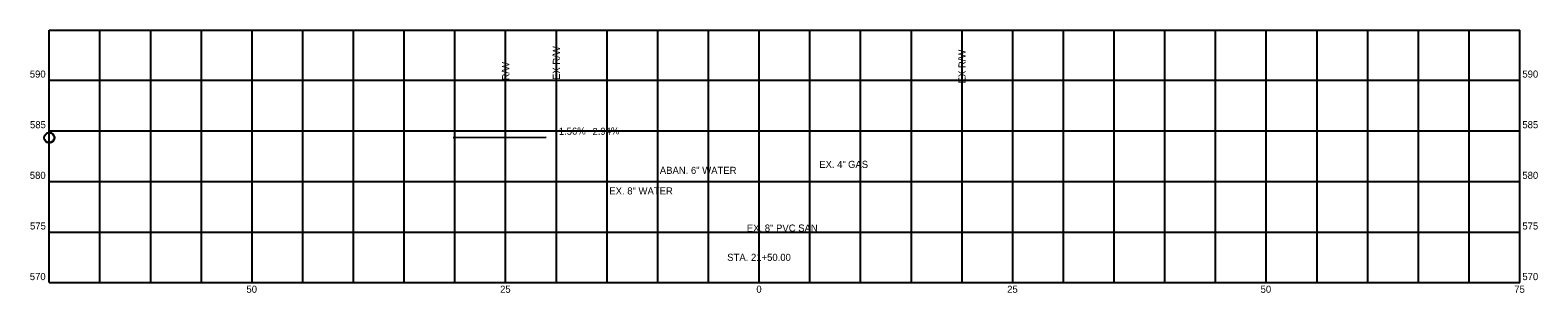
# Model space of a CAD drawing. Extents: x -72 to 1946739, y 569 to 153946.
# Drawn here: x -71.9 to 76.8, y 569 to 594.9 of the extents above; entities that cross this region are included whole.
import ezdxf

# ---------------------------------------------------------------- set-up
doc = ezdxf.new("R2010")
doc.units = 0
for name, color, linetype in [('Default', 7, 'Continuous'), ('DT_X_Contour_Major', 7, 'Continuous'), ('DT_X_Contour_Minor', 7, 'Continuous'), ('DT_X_Terrain_Boundary', 7, 'Continuous'), ('DT_X_Terrain_Ground_Line', 7, 'Continuous'), ('DT_X_Triangles', 7, 'Continuous'), ('DT_X_Void', 7, 'Continuous'), ('PV_X_Curb', 7, 'Continuous'), ('PV_X_EOP', 7, 'Continuous'), ('PV_X_Shoulder', 7, 'Continuous')]:
    doc.layers.add(name, color=color, linetype=linetype)

msp = doc.modelspace()

# ---------------------------------------------------------------- linework, layer by layer
at = {"layer": 'DT_X_Contour_Major'}
msp.add_line((-21.02, 584.32), (-30.18, 584.31), dxfattribs=at)
at = {"layer": 'DT_X_Contour_Minor'}
for p, q in [((-70, 594.94), (75, 594.94)), ((-70, 570), (-70, 594.94)), ((-65, 570), (-65, 594.94)), ((-60, 570), (-60, 594.94)), ((-55, 570), (-55, 594.94)), ((-50, 570), (-50, 594.94)), ((-45, 570), (-45, 594.94)), ((-40, 570), (-40, 594.94)), ((-35, 570), (-35, 594.94)), ((-30, 570), (-30, 594.94)), ((-25, 570), (-25, 594.94)), ((-20, 570), (-20, 594.94)), ((-15, 570), (-15, 594.94)), ((-10, 570), (-10, 594.94)), ((-5, 570), (-5, 594.94)), ((0, 570), (0, 594.94)), ((5, 570), (5, 594.94)), ((10, 570), (10, 594.94)), ((15, 570), (15, 594.94)), ((20, 570), (20, 594.94)), ((25, 570), (25, 594.94)), ((30, 570), (30, 594.94)), ((35, 570), (35, 594.94)), ((40, 570), (40, 594.94)), ((45, 570), (45, 594.94)), ((50, 570), (50, 594.94)), ((55, 570), (55, 594.94)), ((60, 570), (60, 594.94)), ((65, 570), (65, 594.94)), ((70, 570), (70, 594.94)), ((75, 570), (75, 594.94)), ((-70, 590), (75, 590)), ((-70, 585), (75, 585)), ((-70, 580), (75, 580)), ((-70, 575), (75, 575)), ((-70, 570), (75, 570))]:
    msp.add_line(p, q, dxfattribs=at)
at = {"layer": 'DT_X_Void'}
for centre in [(-70, 584.32), (-70, 584.29), (-70, 584.29)]:
    msp.add_circle(centre, 0.5, dxfattribs=at)
at = {"layer": 'PV_X_EOP'}
msp.add_line((-25, 584.62), (-25, 589.62), dxfattribs=at)
at = {"layer": 'PV_X_Shoulder'}
for p, q in [((-20, 584.67), (-20, 589.67)), ((20, 584.33), (20, 589.33))]:
    msp.add_line(p, q, dxfattribs=at)

# ---------------------------------------------------------------- texts
at = {"layer": 'Default'}
for s, rotation, p in [('1.56%', 0.8937, (-19.76, 584.59)), ('2.94%', 1.6832, (-16.43, 584.57))]:
    msp.add_text(s, height=0.7, rotation=rotation, dxfattribs=at).set_placement(p)
at = {"layer": 'DT_X_Terrain_Boundary'}
for s, p in [('590', (-71.92, 590.25)), ('590', (75.25, 590.25)), ('585', (-71.9, 585.25)), ('585', (75.25, 585.25)), ('580', (-71.92, 580.25)), ('580', (75.25, 580.25)), ('575', (-71.9, 575.25)), ('575', (75.25, 575.25)), ('STA. 21+50.00', (-3.15, 572.15)), ('570', (-71.92, 570.25)), ('570', (75.25, 570.25)), ('50', (-50.56, 569)), ('25', (-25.55, 569)), ('0', (-0.28, 569)), ('25', (24.45, 569)), ('50', (49.44, 569)), ('75', (74.45, 569))]:
    msp.add_text(s, height=0.7, dxfattribs=at).set_placement(p)
at = {"layer": 'DT_X_Terrain_Ground_Line'}
for s, p in [('ABAN. 6" WATER', (-9.8, 580.74)), ('EX. 8" WATER', (-14.78, 578.71))]:
    msp.add_text(s, height=0.7, dxfattribs=at).set_placement(p)
at = {"layer": 'DT_X_Triangles'}
for s, p in [('EX. 4"', (5.92, 581.33)), ('GAS', (8.76, 581.33))]:
    msp.add_text(s, height=0.7, dxfattribs=at).set_placement(p)
at = {"layer": 'PV_X_Curb'}
msp.add_text('EX. 8" PVC SAN', height=0.7, dxfattribs=at).set_placement((-1.22, 575.04))
at = {"layer": 'PV_X_EOP'}
msp.add_text('R/W', height=0.7, rotation=90, dxfattribs=at).set_placement((-24.65, 589.97))
at = {"layer": 'PV_X_Shoulder'}
for p in [(-19.65, 590.02), (20.35, 589.68)]:
    msp.add_text('EX R/W', height=0.7, rotation=90, dxfattribs=at).set_placement(p)

doc.saveas('drawing.dxf')
